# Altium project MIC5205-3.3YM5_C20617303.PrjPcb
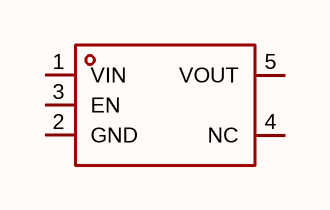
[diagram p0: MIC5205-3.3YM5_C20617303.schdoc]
1 sheet, 1 parts. Net scope: global (net labels, ports and power ports of the same name join across sheets).

## Sheet MIC5205-3.3YM5_C20617303.schdoc
size 127 x 101 mm

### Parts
U?  mic5205-3.3ym5  [SOT-23-5_L2.9-W1.6-P0.95-LS2.8-BR]  (value not drawn)

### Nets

Not connected (* = marked no-connect by the designer): U? 1(VIN) 2(GND) 3(EN) 4(NC) 5(VOUT)

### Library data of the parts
U? = mic5205-3.3ym5: 输出极性:正极;工作电压:20V;输出电压:3.3V;输出电流:150mA;电源纹波抑制比(PSRR):70dB@(1kHz);输出类型:固定;; Manufacturer: TECH PUBLIC(台舟); Symbol: MIC5205-3.3YM5_C20617303; AddInBom: yes; ModelId: 7ba65df16e7b4570af156e925f9c37fe; ModelTransform: 114.173,114.173,0,90,0,0,0,0,0; Output Configuration: 正极; Voltage - Supply: 20V; Output Voltage: 3.3V; Output Current: 150mA; Voltage Dropout: 200mV@(50mA); standby current: 2uA; Output Type: 固定; Number of Outputs: 1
